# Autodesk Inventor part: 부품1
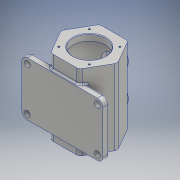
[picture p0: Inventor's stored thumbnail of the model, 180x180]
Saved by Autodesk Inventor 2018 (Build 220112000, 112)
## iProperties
Created: 2021-06
Part Number: 부품1
Material: 알루미늄 6061
Document SubType Name: Modeling
Designer: 1class19
Density: 2.7 g/cm^3
Appearance: 알루미늄 - 평지
Mass: 1495.32 g
Surface Area: 1102.36 cm^2
Volume: 553.824 cm^3
Author: 1class19
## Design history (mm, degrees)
sketch "스케치1"
  geometry: L1 (-52.5, 0)-(-26.25, 45.466); L2 (-26.25, 45.466)-(26.25, 45.466); L3 (26.25, 45.466)-(52.5, 0); L4 (52.5, 0)-(26.25, -45.466); L5 (26.25, -45.466)-(-26.25, -45.466); L6 (-26.25, -45.466)-(-52.5, 0); 2 further points
  constraints: 12 end point, 13 other
extrude "돌출1" new body sketch "스케치1" stored distance "d1" = 140; taper "d2" = 0 deg
node "작업 평면1"
sketch "스케치2"
  geometry: L1 (-52.5, 70)-(-52.5, 45); L2 (-52.5, -70)-(-52.5, -55); L3 (26.25, 70)-(-26.25, 70) reference; L4 (75, 45)-(-75, 45); L5 (75, 45)-(75, -55); L6 (75, -55)-(-75, -55); L7 (-75, -55)-(-75, 45); 1 further point
  constraints: 12 end point, 1 horizontal, 1 perpendicular
  dimensions: "d4" = 25 distance of L1.start L1.end; "d5" = 15 distance of L2.start L2.end; "d8" = 150 distance of L4.start L4.end; "d9" = 150 distance of L5.end L6.end
extrude "돌출2" join sketch "스케치2" distance "d10" = 12; taper "d11" = 0 deg
sketch "스케치3"
  geometry: L1 (26.25, 70)-(-26.25, 70) reference; L2 (0, 70)-(0, 30); L3 (0, 30)-(0, -30); C1 r 20 at (0, 30); C2 r 20 at (0, -30); 1 further point
  constraints: 4 end point, 2 centre point, 2 coincident, 1 midpoint, 1 point on line, 1 vertical
  dimensions: "d12" = 40 distance of L2.start L2.end; "d13" = 60 distance of L2.end L3.end; "d14" = 40 diameter of C1; "d15" = 40 diameter of C2
extrude "돌출3" join sketch "스케치3" distance "d16" = 52.5; taper "d17" = 0 deg
sketch "스케치4"
  geometry: C1 r 20 at (0, 60) reference; C2 r 15 at (0, 60); C3 r 15 at (0, 0); 1 further point
  constraints: 2 centre point, 1 coincident
  dimensions: "d18" = 30 diameter of C2; "d19" = 30 diameter of C3
extrude "돌출4" cut sketch "스케치4" distance "d20" = 8; taper "d21" = 0 deg
sketch "스케치5"
  geometry: C1 r 15 at (0, 60) reference; C2 r 12.5 at (0, 60); C3 r 12.5 at (0, 0); 1 further point
  constraints: 2 centre point, 1 coincident
  dimensions: "d23" = 25 diameter of C2; "d24" = 25 diameter of C3
extrude "돌출5" cut sketch "스케치5" distance "d25" = 30; taper "d26" = 0 deg
sketch "스케치6"
  geometry: C1 r 30 at (0, 0); 1 further point
  constraints: 1 centre point, 1 coincident
  dimensions: "d27" = 60 diameter of C1
extrude "돌출6" cut sketch "스케치6" distance "d28" = 12; taper "d29" = 0 deg
sketch "스케치7"
  geometry: C1 r 30 at (0, 0); 1 further point
  constraints: 1 centre point, 1 coincident
  dimensions: "d30" = 60 diameter of C1
extrude "돌출7" cut sketch "스케치7" distance "d31" = 12; taper "d32" = 0 deg
sketch "스케치8"
  geometry: C1 r 37.5 at (0, 0); 1 further point
  constraints: 1 centre point, 1 coincident
  dimensions: "d33" = 75 diameter of C1
extrude "돌출8" cut sketch "스케치8" distance "d34" = 116; taper "d35" = 0 deg
fillet "모깎기1" dims "d36" = 10
sketch "스케치9"
  geometry: C1 r 5.5 at (65, 45); C2 r 5.5 at (65, -35); C3 r 5.5 at (-65, 45); C4 r 5.5 at (-65, -35); A1 r 10 centre (65, 45) between (75, 45) and (65, 55) reference; A2 r 10 centre (65, -35) between (65, -45) and (75, -35) reference; A3 r 10 centre (-65, 45) between (-65, 55) and (-75, 45) reference; A4 r 10 centre (-65, -35) between (-75, -35) and (-65, -45) reference; 1 further point
  constraints: 4 centre point, 4 coincident
  dimensions: "d37" = 11 diameter of C1; "d38" = 11 diameter of C2; "d39" = 11 diameter of C3; "d40" = 11 diameter of C4
extrude "돌출9" cut sketch "스케치9" distance "d41" = 116; taper "d42" = 0 deg
sketch "스케치10" dims "d43" = 80
  geometry: L1 (0, 0)-(61.24, 61.24); L2 (0, 0)-(86.607, 0); 2 further points
  constraints: 4 end point, 1 coincident, 1 equal length, 1 horizontal, 1 point on line, 3 other
  dimensions: "d44" = 45 deg angle of L2 L1
hole "구멍1" sketch "스케치10" at (28.284, 28.284) diameter "d45" = 3.242; stored, may be unused: countersink angle "d49" = 90 deg, drill point angle "d51" = 118 deg; dims "d46" = 8, "d47" = 4, "d48" = 2, "d50" = 10
sketch "스케치11" dims "d55" = 80
  geometry: 3 further points
  constraints: 1 coincident, 1 vertical alignment, 2 other
hole "구멍2" sketch "스케치11" at (0, 40) diameter "d56" = 3.242; stored, may be unused: countersink angle "d60" = 90 deg, drill point angle "d62" = 118 deg; dims "d57" = 8, "d58" = 4, "d59" = 2, "d61" = 10
fillet "모깎기2" dims "d66" = 3
fillet "모깎기3" dims "d67" = 8
fillet "모깎기4" dims "d68" = 8
fillet "모깎기5" dims "d69" = 3
fillet "모깎기6" dims "d70" = 5
chamfer "모따기1" distance "d71" = 1; stored, may be unused: second distance "d72" = 2, angle "d73" = 45 deg
sketch "스케치12"
  geometry: L1 (-75, 45)-(-75, -35) reference; L2 (-65, -45)-(-32.293, -45) reference; 2 further points
  constraints: 1 other
  dimensions: "d74" = 14 distance from line of L1 point (-61, 5); "d75" = 50 distance from line of L2 point (-61, 5)
feature "엠보싱1" sketch "스케치12" dims "d76" = 0.5, "d77" = 0
node "솔리드1"
pattern_circular "원형 패턴1" dims angle "d53" = 360 deg
pattern_circular "원형 패턴2" dims angle "d64" = 360 deg
